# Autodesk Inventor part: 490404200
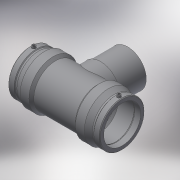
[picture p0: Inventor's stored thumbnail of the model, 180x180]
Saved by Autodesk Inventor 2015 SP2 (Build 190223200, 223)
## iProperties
Created: 2017-06
Part Number: 490404200
Material: Generic
Description: PLASSON TEE 200-200-200
Document SubType Name: Modeling
Designer: KIM
Mass: 9339.42 g
Surface Area: 8252.46 cm^2
Volume: 9339.42 cm^3
Density: 1 g/cm^3
Appearance: Default
Author: KIM
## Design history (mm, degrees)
derived "490404.ipt"
feature "Solid1::490404.ipt"
tag "TaggingFeature1"
body "Solid1"
other parameters: "d0" = 451, "d2" = 261, "d3" = 114, "d4" = 112.75, "d5" = 234.9, "d8" = 168 deg, "d10" = 45.6, "d11" = 15.2, "d13" = 451, "d14" = 17.6296, "d19" = 3.52592, "d20" = 168 deg, "d22" = 242.73, "d23" = 261, "d24" = 235.4481, "d25" = 135 deg, "d26" = 315.7, "d27" = 135 deg, "d29" = 125, "d30" = 15, "d31" = 180.4, "d34" = 5 deg, "d35" = 15, "d39" = 5 deg, "d40" = 9.6, "d41" = 4.8, "d42" = 6, "d43" = 0, "d45" = 4, "d46" = 14, "d47" = 0, "d48" = -265, "d51" = 0, "d54" = 0, "d55" = 234.9, "d56" = 261, "d57" = 157.85, "d58" = 135 deg, "d59" = 114, "d60" = 114, "d61" = 135 deg, "d62" = 265, "d72" = 220.99, "d73" = 110.495, "d74" = -265, "d77" = 0, "d80" = 0, "d82" = 134.5, "d83" = 0, "d84" = 3, "d85" = 0, "d86" = 3, "d87" = 0, "d88" = 33.06, "d89" = 8.265, "d90" = 33.06, "L_" = 451, "L_1" = 114, "D_" = 261, "A_" = 125, "d_2" = 12, "H_" = 265
